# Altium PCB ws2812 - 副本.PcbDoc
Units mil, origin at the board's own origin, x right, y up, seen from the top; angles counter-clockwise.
Board outline 1181.1 x 1181.1 mil, 2 copper layers (Top Layer, Bottom Layer); 13 components, 13 nets, 46 pads, 19 vias.
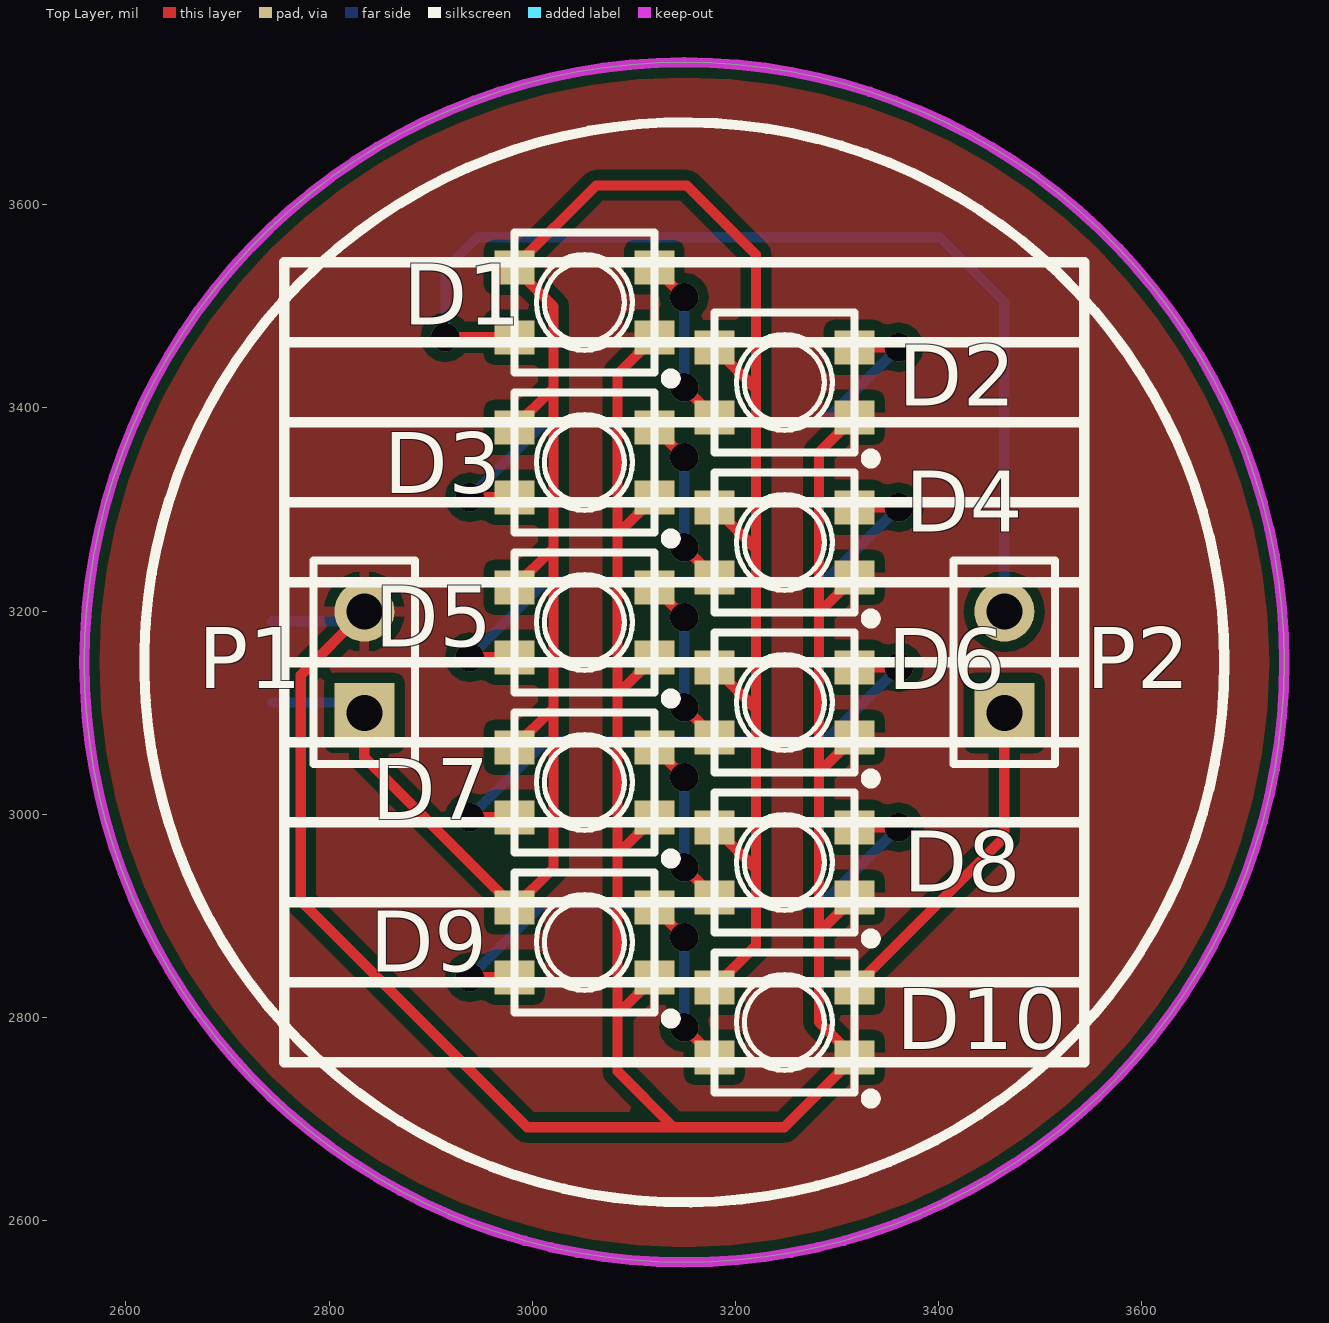
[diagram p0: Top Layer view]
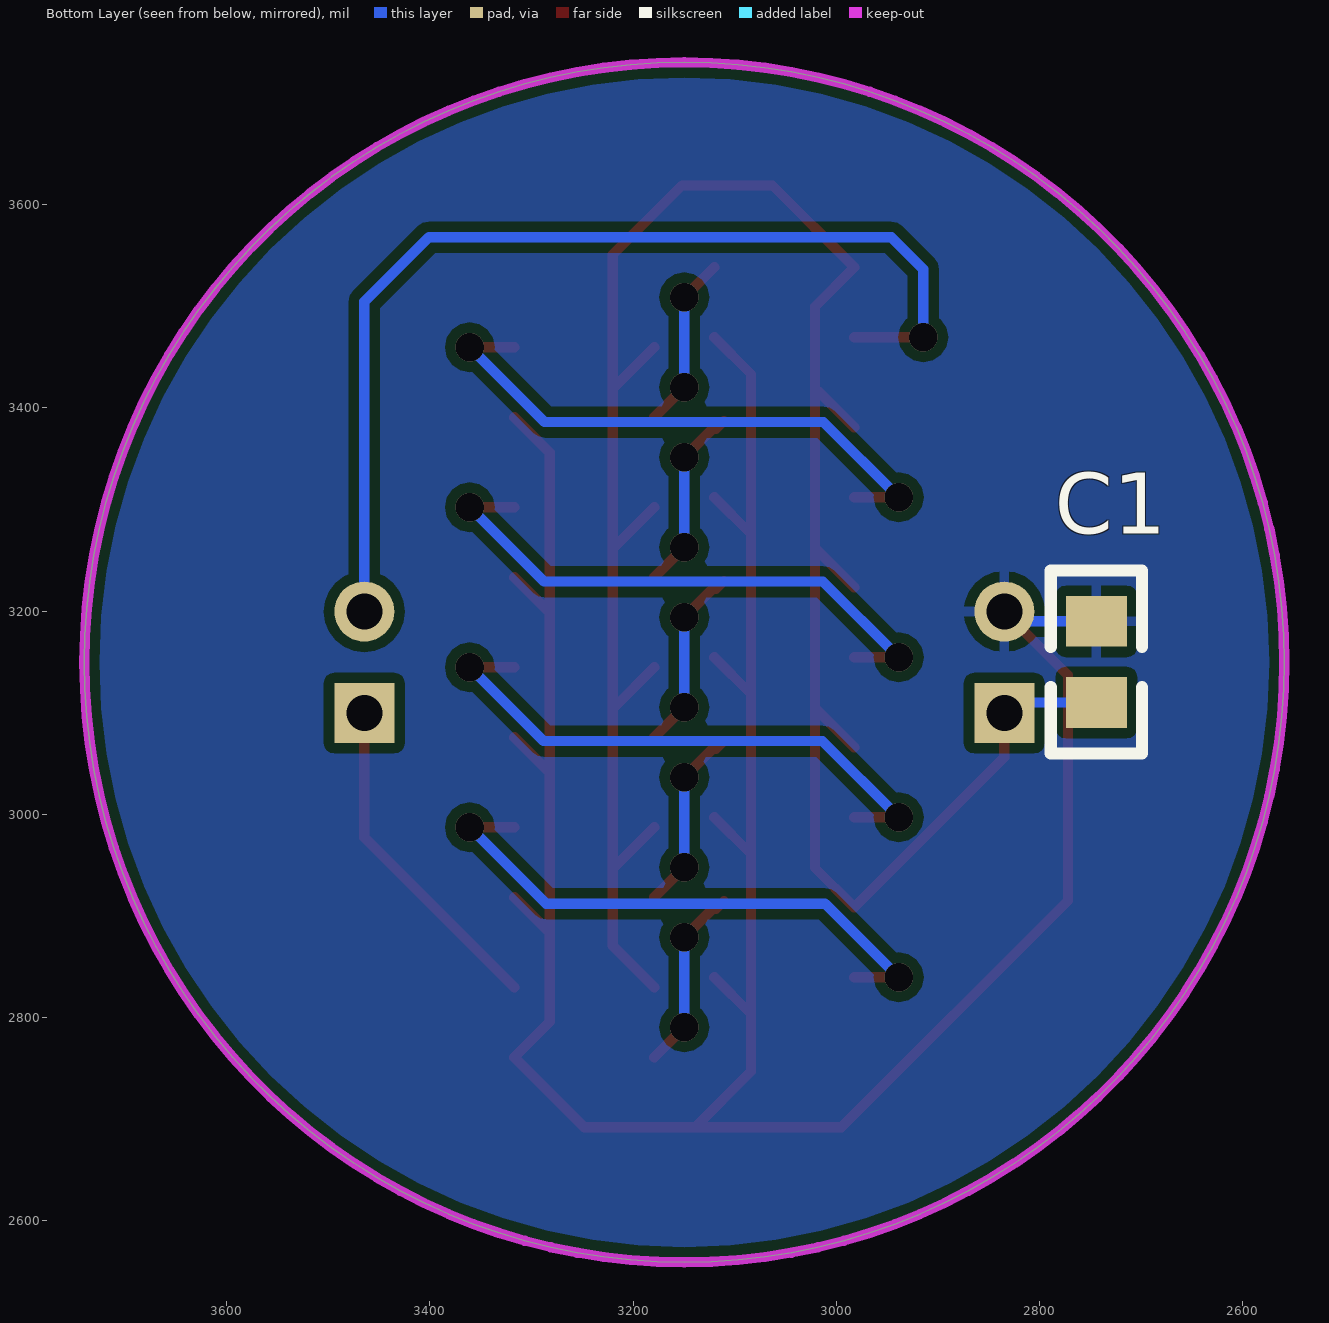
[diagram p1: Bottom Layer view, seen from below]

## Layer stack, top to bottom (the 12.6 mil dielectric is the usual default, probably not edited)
Top Solder: solder mask 0.4, Solder Resist, Dk 3.5
Top Layer: signal copper 1.4
Dielectric 1: dielectric 12.6, FR-4, Dk 4.8
Bottom Layer: signal copper 1.4
Bottom Solder: solder mask 0.4, Solder Resist, Dk 3.5

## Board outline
3149.61,2559.06 cw(c3149.61,3149.61) 2559.06,3149.61 cw(c3149.61,3149.61) 3149.61,3740.16 cw(c3149.61,3149.61) 3740.16,3149.61 cw(c3149.61,3149.61)

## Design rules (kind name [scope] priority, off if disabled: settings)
Clearance [All] p1: gap=10 ignorepadtopadclearanceinfootprint=FALSE except(0: Arc-Hole Track-Hole SMDPad-Hole THPad-Hole Via-Hole Fill-Hole Poly-Hole Region-Hole Text-Hole)
ComponentClearance [All] p1: gap=0 collisioncheckmode=3 verticalgap=0 showdistances=FALSE
PolygonConnect [All] p1: connectstyle=Relief reliefconductorwidth=10 reliefentries=4 polygonreliefangle="90 Angle" airgapwidth=10
RoutingVias [All] p1: holewidth=28 width=50 viastyle="Through Hole" minholewidth=28 minwidth=50 maxholewidth=28 maxwidth=50
SolderMaskExpansion [All] p1: expansion=4
Width [All] p1: maxlimit=10 minlimit=10 preferedwidth=10
29 further rules are at their usual default settings.

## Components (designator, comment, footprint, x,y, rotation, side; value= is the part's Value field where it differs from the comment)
C1 "4.7uF" 0805 2744,3190 r270 bottom
D1 "wss2812" LED-3535-RGB 3051.18,3503.94 r0 top
D2 "wss2812" LED-3535-RGB 3248.03,3425.2 r0 top
D3 "wss2812" LED-3535-RGB 3051.18,3346.46 r0 top
D4 "wss2812" LED-3535-RGB 3248.03,3267.72 r0 top
D5 "wss2812" LED-3535-RGB 3051.18,3188.98 r0 top
D6 "wss2812" LED-3535-RGB 3248.03,3110.24 r0 top
D7 "wss2812" LED-3535-RGB 3051.18,3031.5 r0 top
D8 "wss2812" LED-3535-RGB 3248.03,2952.76 r0 top
D9 "wss2812" LED-3535-RGB 3051.18,2874.02 r0 top
D10 "wss2812" LED-3535-RGB 3248.03,2795.28 r0 top
P1 "Header 2" HDR1X2 2834.65,3099.61 r90 top
P2 "Header 2" HDR1X2 3464.57,3099.61 r90 top

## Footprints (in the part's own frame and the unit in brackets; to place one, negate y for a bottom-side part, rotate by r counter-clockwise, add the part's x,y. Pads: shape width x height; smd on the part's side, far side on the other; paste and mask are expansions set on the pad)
0805 [mil]
  rect 50x60 smd: 1(0,0) 2(80,0)
  silkscreen extent -50,-45 130,45
HDR1X2 [mm] "Connector; Header; 2 Position"
  rect 1.5x1.5 hole 0.9: 1(0,0)
  round 1.5 hole 0.9: 2(2.54,0)
  silkscreen extent -1.27,-1.27 3.81,1.27
LED-3535-RGB [mm]
  rect 1x0.85 smd: 1(-1.75,0.875) 2(-1.75,-0.875) 3(1.75,-0.875) 4(1.75,0.875)
  silkscreen extent -1.75,-2.03 2.29,1.75

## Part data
C1: library part Cap, "Capacitor"
P1 P2: "Header, 2-Pin"

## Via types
v1: diameter 28, hole 28, Top Layer to Bottom Layer, 19 vias

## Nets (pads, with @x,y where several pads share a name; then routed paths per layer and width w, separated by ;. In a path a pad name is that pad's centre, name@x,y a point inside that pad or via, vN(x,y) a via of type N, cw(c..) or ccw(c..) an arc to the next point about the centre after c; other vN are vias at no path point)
"Data IN": D10.4 P2.1 | length 331
  Top Layer w10: D10.4 3464.57,2977.36 P2.1
"Data OUT": D1.2 P2.2 | length 1029.1
  Top Layer w10: v1(2914.51,3469.49) D1.2
  Bottom Layer w10: v1(2914.51,3469.49) 2914.51,3536.51 2946,3568 3401,3568 3464.57,3504.43 P2.2
GND: C1.1 D1.3 D2.3 D3.3 D4.3 D5.3 D6.3 D7.3 D8.3 D9.3 D10.3 P1.2 | length 2897.1
  Top Layer w10: P1.2 2772,3136.96 2772,2915 2995,2692 3139,2692 ; D9.3 3084,2803.49 ; D7.3 3084,2960.97 ; D5.3 3084,3118.45 ; D3.3 3084,3275.93 ; D1.3 3084,3433.41 3084,3275.93 ; D8.3 3282,2883.38 ; D6.3 3282,3040.86 ; D4.3 3282.66,3199 3282,3199 ; D2.3 3282,3355.82 3282,3199 ; 3084,2803.49 3084,2960.97 ; 3084,2803.49 3084,2747 3139,2692 ; 3084,2960.97 3084,3118.45 ; 3084,3118.45 3084,3275.93 ; 3139,2692 3248.1,2692 D10.3 3282,2795.76 3282,2883.38 ; 3282,2883.38 3282,3040.86 ; 3282,3040.86 3282,3199
  Bottom Layer w10: C1.1 2825.04,3190 P1.2
NetD1_4: D1.4 D2.2 | length 172.1
  Top Layer w10: D1.4 v1(3149.61,3508.86) ; v1(3149.61,3420.28) D2.2
  Bottom Layer w10: v1(3149.61,3420.28) v1(3149.61,3508.86)
NetD2_4: D2.4 D3.2 | length 570.7
  Top Layer w10: v1(2938.57,3312.01) D3.2 ; D2.4 v1(3360.65,3459.65)
  Bottom Layer w10: v1(2938.57,3312.01) 3012.56,3386 3287,3386 v1(3360.65,3459.65)
NetD3_4: D3.4 D4.2 | length 183.2
  Top Layer w10: D3.4@3110.47,3387.05 D3.4@3118.35,3379.17 ; D3.4 v1(3149.61,3351.38) ; v1(3149.61,3262.8) D4.2
  Bottom Layer w10: v1(3149.61,3262.8) v1(3149.61,3351.38)
NetD4_4: D4.4 D5.2 | length 570.7
  Top Layer w10: v1(2938.57,3154.53) D5.2 ; D4.4 v1(3360.65,3302.17)
  Bottom Layer w10: v1(2938.57,3154.53) 3013.04,3229 3287.48,3229 v1(3360.65,3302.17)
NetD5_4: D5.4 D6.2 | length 183.2
  Top Layer w10: D5.4@3110.47,3229.57 D5.4@3118.35,3221.69 ; D5.4 v1(3149.61,3193.9) ; v1(3149.61,3105.31) D6.2
  Bottom Layer w10: v1(3149.61,3105.31) v1(3149.61,3193.9)
NetD6_4: D6.4 D7.2 | length 570.7
  Top Layer w10: v1(2938.57,2997.05) D7.2 ; D6.4 v1(3360.65,3144.68)
  Bottom Layer w10: v1(2938.57,2997.05) 3013.52,3072 3287.96,3072 v1(3360.65,3144.68)
NetD7_4: D7.4 D8.2 | length 183.2
  Top Layer w10: D7.4@3110.47,3072.09 D7.4@3118.35,3064.21 ; D7.4 v1(3149.61,3036.42) ; v1(3149.61,2947.83) D8.2
  Bottom Layer w10: v1(3149.61,2947.83) v1(3149.61,3036.42)
NetD8_4: D8.4 D9.2 | length 570.7
  Top Layer w10: v1(2938.57,2839.57) D9.2 ; D8.4 v1(3360.65,2987.2)
  Bottom Layer w10: v1(2938.57,2839.57) 3011,2912 3285.44,2912 v1(3360.65,2987.2)
NetD9_4: D9.4 D10.2 | length 183.2
  Top Layer w10: D9.4@3110.47,2914.61 D9.4@3118.35,2906.73 ; D9.4 v1(3149.61,2878.94) ; v1(3149.61,2790.35) D10.2
  Bottom Layer w10: v1(3149.61,2790.35) v1(3149.61,2878.94)
VCC: C1.2 D1.1 D2.1 D3.1 D4.1 D5.1 D6.1 D7.1 D8.1 D9.1 D10.1 P1.1 | length 2440.2
  Top Layer w10: P1.1 2834.65,3056.1 D9.1 3021,2947.18 3021,3104 ; D7.1 3020.34,3104 3021,3104 ; D5.1 3020.86,3262 3021,3262 ; D3.1 3018.38,3417 3021,3417 ; D10.1 3220,2870.59 3220,2946.34 ; D8.1 3220,2946.34 ; D6.1 3218.82,3105 3220,3105 ; D4.1 3220,3261.3 ; D2.1 3220,3418.78 ; 3021,3104 3021,3262 ; 3021,3262 3021,3417 ; 3021,3417 3021,3499.67 D1.1 3062.9,3619 3152,3619 3220,3551 3220,3418.78 ; 3220,2946.34 3220,3105 ; 3220,3105 3220,3261.3 ; 3220,3261.3 3220,3418.78
  Bottom Layer w10: C1.2 2824.25,3110 P1.1

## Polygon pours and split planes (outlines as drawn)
GND on Bottom Layer "Bottom Layer-No Net" (solid, remove dead copper, pour order 2): 2284,4000 2292,4008 3945,4008 3945,2486 3925,2466 3880,2511 2259,2511
GND on Top Layer "Bottom Layer-No Net" (solid, remove dead copper, pour order 4): 2391,3839 3990,3839 4082,3747 4082,2400 2441,2400 2311,2530

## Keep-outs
Keep-Out Layer:
  circle w10: c3149.61,3149.61 r590.55

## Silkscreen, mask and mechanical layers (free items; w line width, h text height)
Top Overlay:
  circle w10: c3149.61,3149.61 r531.5
  lines w10: 2755.91,2834.65 3543.31,2834.65 ; 2755.91,2913.39 3543.31,2913.39 ; 2755.91,2992.13 3543.31,2992.13 ; 2755.91,3070.87 3543.31,3070.87 ; 2755.91,3149.61 3543.31,3149.61 ; 2755.91,3228.35 3543.31,3228.35 ; 2755.91,3307.09 3543.31,3307.09 ; 2755.91,3385.83 3543.31,3385.83 ; 2755.91,3464.57 3543.31,3464.57 ; 2755.91,2755.91 3543.31,2755.91 3543.31,3543.31 2755.91,3543.31 2755.91,2755.91
Mechanical 1:
  circle w10: c3149.61,3149.61 r590.55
